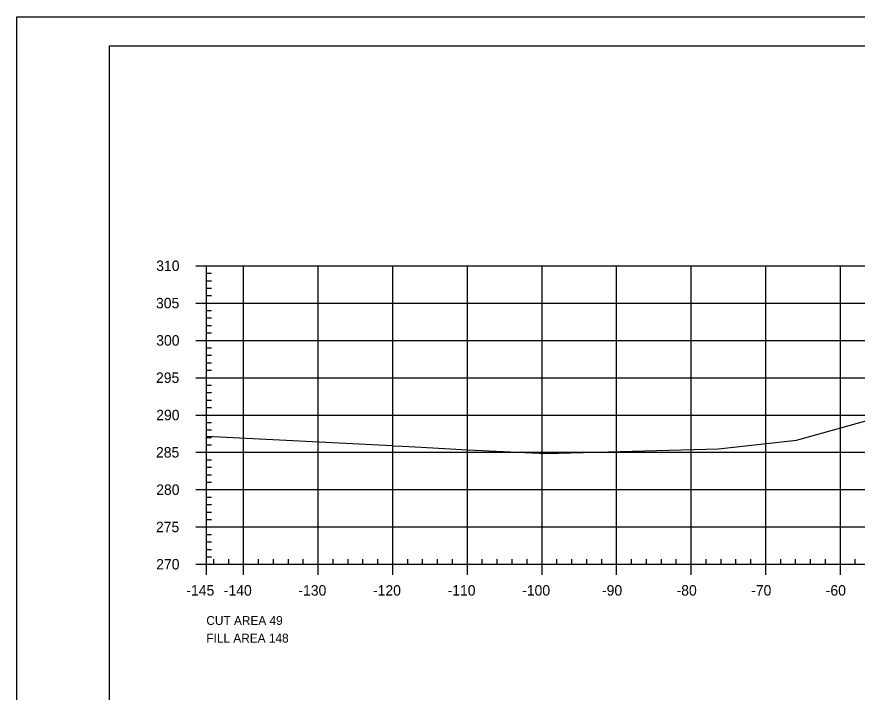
# Model space of a CAD drawing. Extents: x 1370843 to 1371177, y 380307 to 382654.
# Drawn here: x 1370843.3 to 1370956, y 381923.7 to 382014.2 of the extents above; entities that cross this region are included whole.
import ezdxf

# ---------------------------------------------------------------- set-up
doc = ezdxf.new("R2010")
doc.units = 0
for name, color, linetype in [('R_Axis', 7, 'Continuous'), ('R_Axis Annot', 7, 'Continuous'), ('R_Border', 7, 'Continuous'), ('R_Border Notes', 7, 'Continuous'), ('R_Exist Surface', 7, 'Continuous'), ('R_Grid', 7, 'Continuous'), ('R_No Plot', 7, 'Continuous')]:
    doc.layers.add(name, color=color, linetype=linetype)

msp = doc.modelspace()

# ---------------------------------------------------------------- linework, layer by layer
at = {"layer": 'R_Axis'}
for p, q in [((1370867.31, 381980.81), (1370868.71, 381980.81)), ((1370868.71, 381940.81), (1370868.71, 381980.81)), ((1370868.71, 381979.81), (1370869.41, 381979.81)), ((1370868.71, 381978.81), (1370869.41, 381978.81)), ((1370868.71, 381977.81), (1370869.41, 381977.81)), ((1370868.71, 381976.81), (1370869.41, 381976.81)), ((1370867.31, 381975.81), (1370868.71, 381975.81)), ((1370868.71, 381974.81), (1370869.41, 381974.81)), ((1370868.71, 381973.81), (1370869.41, 381973.81)), ((1370868.71, 381972.81), (1370869.41, 381972.81)), ((1370868.71, 381971.81), (1370869.41, 381971.81)), ((1370867.31, 381970.81), (1370868.71, 381970.81)), ((1370868.71, 381969.81), (1370869.41, 381969.81)), ((1370868.71, 381968.81), (1370869.41, 381968.81)), ((1370868.71, 381967.81), (1370869.41, 381967.81)), ((1370868.71, 381966.81), (1370869.41, 381966.81)), ((1370867.31, 381965.81), (1370868.71, 381965.81)), ((1370868.71, 381964.81), (1370869.41, 381964.81)), ((1370868.71, 381963.81), (1370869.41, 381963.81)), ((1370868.71, 381962.81), (1370869.41, 381962.81)), ((1370868.71, 381961.81), (1370869.41, 381961.81)), ((1370867.31, 381960.81), (1370868.71, 381960.81)), ((1370868.71, 381959.81), (1370869.41, 381959.81)), ((1370868.71, 381958.81), (1370869.41, 381958.81)), ((1370868.71, 381957.81), (1370869.41, 381957.81)), ((1370868.71, 381956.81), (1370869.41, 381956.81)), ((1370867.31, 381955.81), (1370868.71, 381955.81)), ((1370868.71, 381954.81), (1370869.41, 381954.81)), ((1370868.71, 381953.81), (1370869.41, 381953.81)), ((1370868.71, 381952.81), (1370869.41, 381952.81)), ((1370868.71, 381951.81), (1370869.41, 381951.81)), ((1370867.31, 381950.81), (1370868.71, 381950.81)), ((1370868.71, 381949.81), (1370869.41, 381949.81)), ((1370868.71, 381948.81), (1370869.41, 381948.81)), ((1370868.71, 381947.81), (1370869.41, 381947.81)), ((1370867.31, 381945.81), (1370868.71, 381945.81)), ((1370868.71, 381946.81), (1370869.41, 381946.81)), ((1370868.71, 381944.81), (1370869.41, 381944.81)), ((1370868.71, 381943.81), (1370869.41, 381943.81)), ((1370868.71, 381942.81), (1370869.41, 381942.81)), ((1370868.71, 381941.81), (1370869.41, 381941.81)), ((1370868.71, 381940.81), (1370868.71, 381941.51)), ((1370869.71, 381940.81), (1370869.71, 381941.51)), ((1370871.71, 381940.81), (1370871.71, 381941.51)), ((1370875.71, 381940.81), (1370875.71, 381941.51)), ((1370877.71, 381940.81), (1370877.71, 381941.51)), ((1370879.71, 381940.81), (1370879.71, 381941.51)), ((1370881.71, 381940.81), (1370881.71, 381941.51)), ((1370885.71, 381940.81), (1370885.71, 381941.51)), ((1370887.71, 381940.81), (1370887.71, 381941.51)), ((1370889.71, 381940.81), (1370889.71, 381941.51)), ((1370891.71, 381940.81), (1370891.71, 381941.51)), ((1370895.71, 381940.81), (1370895.71, 381941.51)), ((1370897.71, 381940.81), (1370897.71, 381941.51)), ((1370899.71, 381940.81), (1370899.71, 381941.51)), ((1370901.71, 381940.81), (1370901.71, 381941.51)), ((1370905.71, 381940.81), (1370905.71, 381941.51)), ((1370907.71, 381940.81), (1370907.71, 381941.51)), ((1370909.71, 381940.81), (1370909.71, 381941.51)), ((1370911.71, 381940.81), (1370911.71, 381941.51)), ((1370915.71, 381940.81), (1370915.71, 381941.51)), ((1370917.71, 381940.81), (1370917.71, 381941.51)), ((1370919.71, 381940.81), (1370919.71, 381941.51)), ((1370921.71, 381940.81), (1370921.71, 381941.51)), ((1370925.71, 381940.81), (1370925.71, 381941.51)), ((1370927.71, 381940.81), (1370927.71, 381941.51)), ((1370929.71, 381940.81), (1370929.71, 381941.51)), ((1370931.71, 381940.81), (1370931.71, 381941.51)), ((1370935.71, 381940.81), (1370935.71, 381941.51)), ((1370937.71, 381940.81), (1370937.71, 381941.51)), ((1370939.71, 381940.81), (1370939.71, 381941.51)), ((1370941.71, 381940.81), (1370941.71, 381941.51)), ((1370945.71, 381940.81), (1370945.71, 381941.51)), ((1370947.71, 381940.81), (1370947.71, 381941.51)), ((1370949.71, 381940.81), (1370949.71, 381941.51)), ((1370951.71, 381940.81), (1370951.71, 381941.51)), ((1370955.71, 381940.81), (1370955.71, 381941.51)), ((1370867.31, 381940.81), (1370868.71, 381940.81)), ((1370868.71, 381940.81), (1371158.71, 381940.81)), ((1370868.71, 381939.41), (1370868.71, 381940.81)), ((1370873.71, 381939.41), (1370873.71, 381940.81)), ((1370883.71, 381939.41), (1370883.71, 381940.81)), ((1370893.71, 381939.41), (1370893.71, 381940.81)), ((1370903.71, 381939.41), (1370903.71, 381940.81)), ((1370913.71, 381939.41), (1370913.71, 381940.81)), ((1370923.71, 381939.41), (1370923.71, 381940.81)), ((1370933.71, 381939.41), (1370933.71, 381940.81)), ((1370943.71, 381939.41), (1370943.71, 381940.81)), ((1370953.71, 381939.41), (1370953.71, 381940.81))]:
    msp.add_line(p, q, dxfattribs=at)
at = {"layer": 'R_Border'}
for p, q in [((1370855.71, 382010.27), (1371171.89, 382010.27)), ((1370855.71, 381804.81), (1370855.71, 382010.27))]:
    msp.add_line(p, q, dxfattribs=at)
at = {"layer": 'R_Exist Surface'}
msp.add_line((1370893.64, 381956.7), (1370868.71, 381957.93), dxfattribs=at)
msp.add_lwpolyline([(1370893.64, 381956.7), (1370894.96, 381956.64), (1370896.69, 381956.55), (1370899.08, 381956.43), (1370903.7, 381956.14), (1370914.26, 381955.67), (1370937.35, 381956.29), (1370947.82, 381957.44), (1370956.83, 381959.95), (1370968.62, 381963.14), (1370975.46, 381964.11), (1370975.76, 381964.15), (1370979.05, 381964.22), (1370986.46, 381964.38), (1370987.42, 381964.36), (1370995.77, 381964.15), (1370997.65, 381963.87), (1371003.52, 381962.98), (1371015.98, 381960.2), (1371022.82, 381958.66), (1371046, 381957.73), (1371064.49, 381956.94), (1371069.83, 381956.99)], dxfattribs=at)
at = {"layer": 'R_Grid'}
for p, q in [((1370868.71, 381980.81), (1371158.71, 381980.81)), ((1370868.71, 381940.81), (1370868.71, 381980.81)), ((1370873.71, 381940.81), (1370873.71, 381980.81)), ((1370883.71, 381940.81), (1370883.71, 381980.81)), ((1370893.71, 381940.81), (1370893.71, 381980.81)), ((1370903.71, 381940.81), (1370903.71, 381980.81)), ((1370913.71, 381940.81), (1370913.71, 381980.81)), ((1370923.71, 381940.81), (1370923.71, 381980.81)), ((1370933.71, 381940.81), (1370933.71, 381980.81)), ((1370943.71, 381940.81), (1370943.71, 381980.81)), ((1370953.71, 381940.81), (1370953.71, 381980.81)), ((1370868.71, 381975.81), (1371158.71, 381975.81)), ((1370868.71, 381970.81), (1371158.71, 381970.81)), ((1370868.71, 381965.81), (1371158.71, 381965.81)), ((1370868.71, 381960.81), (1371158.71, 381960.81)), ((1370868.71, 381955.81), (1371158.71, 381955.81)), ((1370868.71, 381950.81), (1371158.71, 381950.81)), ((1370868.71, 381945.81), (1371158.71, 381945.81)), ((1370868.71, 381940.81), (1371158.71, 381940.81))]:
    msp.add_line(p, q, dxfattribs=at)
at = {"layer": 'R_No Plot'}
msp.add_line((1370843.31, 382014.17), (1371176.64, 382014.17), dxfattribs=at)
for points in [[(1370843.3, 382014.17), (1371176.64, 382014.17), (1371176.64, 381800.83), (1370843.3, 381800.83)], [(1371089.63, 382010.27), (1371089.63, 382000.39), (1371125.36, 382000.39), (1371125.36, 381997.47), (1371148.56, 381997.47), (1371148.56, 381973.14), (1371171.89, 381973.14), (1371171.89, 381804.81), (1370855.71, 381804.81), (1370855.71, 382010.27)]]:
    msp.add_lwpolyline(points, close=True, dxfattribs=at)

# ---------------------------------------------------------------- texts
at = {"layer": 'R_Axis Annot'}
for s, p in [('310', (1370861.99, 381980.11)), ('305', (1370861.96, 381975.11)), ('300', (1370861.99, 381970.11)), ('295', (1370861.96, 381965.11)), ('290', (1370861.99, 381960.11)), ('285', (1370861.96, 381955.11)), ('280', (1370861.99, 381950.11)), ('275', (1370861.96, 381945.11)), ('270', (1370861.99, 381940.11)), ('-145', (1370866.03, 381936.61)), ('-140', (1370871.05, 381936.61)), ('-130', (1370881.05, 381936.61)), ('-120', (1370891.05, 381936.61)), ('-110', (1370901.05, 381936.61)), ('-100', (1370911.05, 381936.61)), ('-90', (1370921.75, 381936.61)), ('-80', (1370931.75, 381936.61)), ('-70', (1370941.75, 381936.61)), ('-60', (1370951.75, 381936.61))]:
    msp.add_text(s, height=1.4, dxfattribs=at).set_placement(p)
at = {"layer": 'R_Border Notes'}
for s, p in [('CUT AREA 49', (1370868.71, 381932.68)), ('FILL AREA 148', (1370868.71, 381930.32))]:
    msp.add_text(s, height=1.1875, dxfattribs=at).set_placement(p)

doc.saveas('drawing.dxf')
